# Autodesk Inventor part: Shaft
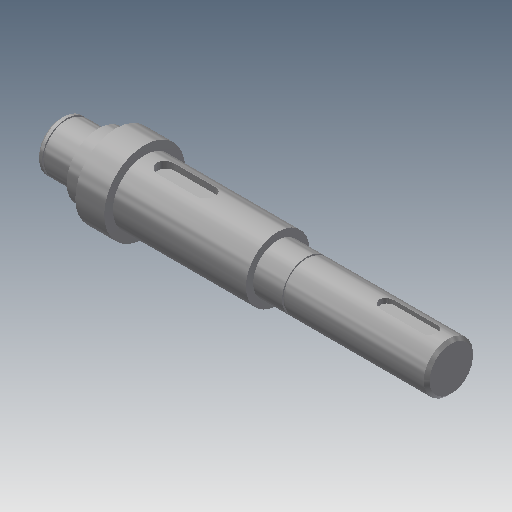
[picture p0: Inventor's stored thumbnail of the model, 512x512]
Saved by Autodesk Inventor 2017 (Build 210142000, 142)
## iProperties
Created: 2019-02
Part Number: Shaft
Material: Steel
Document SubType Name: Modeling
Designer: user
Density: 1 g/cm^3
Appearance: Steel
CustomPartVersion: 1
Author: user
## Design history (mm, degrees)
sketch "Main Sketch"
  geometry: L1 (0, 0)-(135, 0) reference; L2 (0, 0)-(0, 8.5); L3 (0, 8.5)-(13, 8.5); L4 (13, 8.5)-(13, 11); L5 (13, 11)-(19, 11); L6 (19, 11)-(19, 14); L7 (29, 14)-(29, 11); L8 (19, 14)-(29, 14); L9 (75, 11)-(75, 8.5); L10 (29, 11)-(75, 11); L11 (135, 8.5)-(135, 0); L12 (75, 8.5)-(135, 8.5)
  constraints: 24 end point, 6 vertical, 1 horizontal
  dimensions: "d3" = 17 diameter of L3 L1 (derived); "d4" = 22 diameter of L5 L1 (derived); "d5" = 28 diameter of L8 L1 (derived); "d6" = 22 diameter of L10 L1 (derived); "d7" = 17 diameter of L12 L1 (derived)
revolve "Revolution1" sketch "Main Sketch" stored, may be unused: angle "d8" = 0 deg
node "Keyway1"
node "Keyway2"
chamfer "Chamfer3" distance "d15" = 1; stored, may be unused: second distance "d16" = 0.125, angle "d17" = 45 deg
node "Retaining Ring Groove1"
chamfer "Chamfer2" distance "d12" = 1; stored, may be unused: second distance "d13" = 0.125, angle "d14" = 45 deg
node "Retaining Ring Groove2"
body "Solid1"
feature "iFeature27:1"
feature "iFeature27:2"
feature "iFeature3:1"
feature "iFeature3:2"
other parameters: "d0" = 0, "d1" = 0, "d2" = 0
